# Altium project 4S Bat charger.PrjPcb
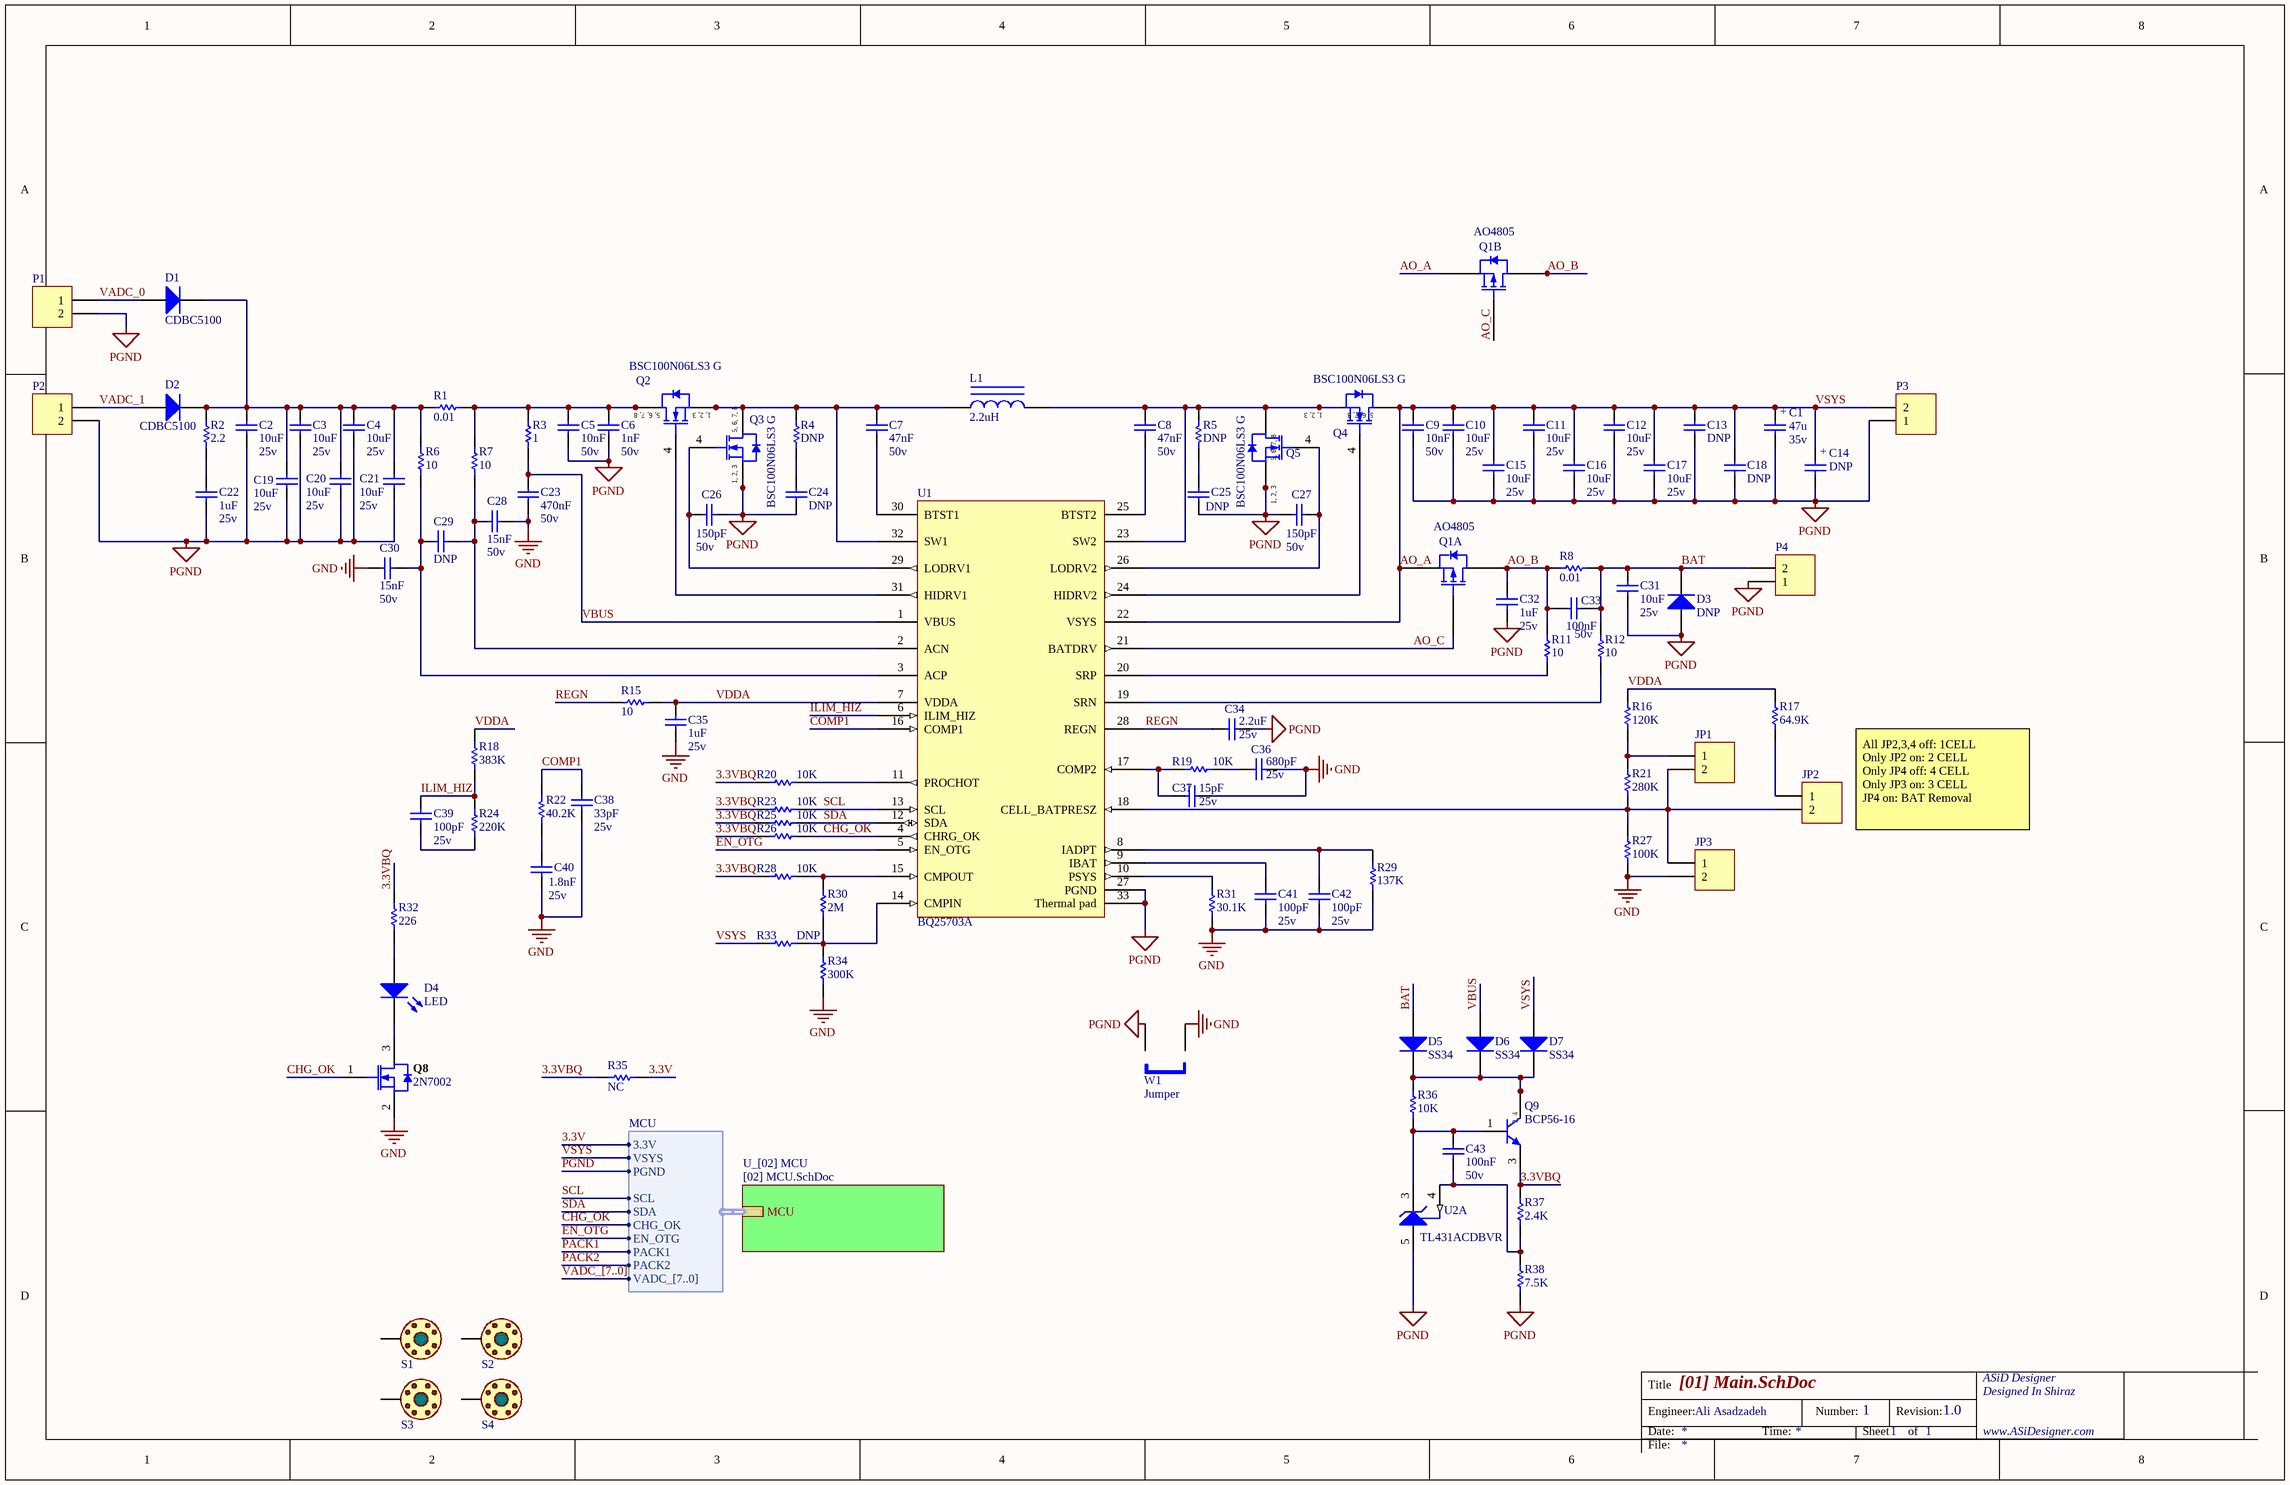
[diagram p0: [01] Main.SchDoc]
2 sheets, 150 parts. Net scope: hierarchical (ports join the sheet entries above them; power ports are global).
Board file: 4S Bat charger.PcbDoc
Sheets:
  [01] Main.SchDoc
    U_[02] MCU = [02] MCU.SchDoc

## Sheet [01] Main.SchDoc: Design 1
size Tabloid; Engineer: The ASID Designer; Organization: ASID Designer; Address1: Iran; Address2: Shiraz; Address3: P.O.Box 71765-385; DocumentNumber: 1; Revision: 1.0; SheetNumber: 1; SheetTotal: 1

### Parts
C1  Volte: 35v  [MY_SMC_D]  (hidden comment: 47u)
C2  Volte: 25v  [MY_0805]  (hidden comment: 10uF)
C3  Volte: 25v  [MY_0805]  (hidden comment: 10uF)
C4  Volte: 25v  [MY_0805]  (hidden comment: 10uF)
C5  Volte: 50v  [MY_0805]  (hidden comment: 10nF)
C6  Volte: 50v  [MY_0805]  (hidden comment: 1nF)
C7  Volte: 50v  [MY_0805]  (hidden comment: 47nF)
C8  Volte: 50v  [MY_0805]  (hidden comment: 47nF)
C9  Volte: 50v  [MY_0805]  (hidden comment: 10nF)
C10  Volte: 25v  [MY_0805]  (hidden comment: 10uF)
C11  Volte: 25v  [MY_0805]  (hidden comment: 10uF)
C12  Volte: 25v  [MY_0805]  (hidden comment: 10uF)
C13  DNP  [MY_0805]
C14  DNP  [MY_SMC_D]
C15  Volte: 25v  [MY_0805]  (hidden comment: 10uF)
C16  Volte: 25v  [MY_0805]  (hidden comment: 10uF)
C17  Volte: 25v  [MY_0805]  (hidden comment: 10uF)
C18  DNP  [MY_0805]
C19  Volte: 25v  [MY_0805]  (hidden comment: 10uF)
C20  Volte: 25v  [MY_0805]  (hidden comment: 10uF)
C21  Volte: 25v  [MY_0805]  (hidden comment: 10uF)
C22  Volte: 25v  [MY_0805]  (hidden comment: 1uF)
C23  Volte: 50v  [MY_0805]  (hidden comment: 470nF)
C24  DNP  [MY_0805]
C25  DNP  [MY_0805]
C26  Volte: 50v  [MY_0805]  (hidden comment: 150pF)
C27  Volte: 50v  [MY_0805]  (hidden comment: 150pF)
C28  Volte: 50v  [MY_0805]  (hidden comment: 15nF)
C29  DNP  [MY_0805]
C30  Volte: 50v  [MY_0805]  (hidden comment: 15nF)
C31  Volte: 25v  [MY_0805]  (hidden comment: 10uF)
C32  Volte: 25v  [MY_0805]  (hidden comment: 1uF)
C33  Volte: 50v  [MY_0805]  (hidden comment: 100nF)
C34  Volte: 25v  [MY_0805]  (hidden comment: 2.2uF)
C35  Volte: 25v  [MY_0805]  (hidden comment: 1uF)
C36  Volte: 25v  [MY_0805]  (hidden comment: 680pF)
C37  Volte: 25v  [MY_0805]  (hidden comment: 15pF)
C38  Volte: 25v  [MY_0805]  (hidden comment: 33pF)
C39  Volte: 25v  [MY_0805]  (hidden comment: 100pF)
C40  Volte: 25v  [MY_0805]  (hidden comment: 1.8nF)
C41  Volte: 25v  [MY_0805]  (hidden comment: 100pF)
C42  Volte: 25v  [MY_0805]  (hidden comment: 100pF)
C43  Volte: 50v  [MY_0805]  (hidden comment: 100nF)
D1  CDBC5100  [MY_SMC]
D2  CDBC5100  [MY_SMC]
D3  DNP  [MY_SMB]
D4  LED  [MY_LED_0805]
D5  SS34  [MY_SMB]
D6  SS34  [MY_SMB]
D7  SS34  [MY_SMB]
JP1  Header 2  [My_1X02]  (value not drawn)
JP2  Header 2  [My_1X02]  (value not drawn)
JP3  Header 2  [My_1X02]  (value not drawn)
L1  2.2uH  [L5mm]
P1  Header 2  [MY_MSTBA2]  (value not drawn)
P2  Header 2  [MY_MSTBA2]  (value not drawn)
P3  Header 2  [MY_MSTBA2]  (value not drawn)
P4  Header 2  [MY_MSTBA2]  (value not drawn)
Q1  AO4805  [My_SOIC_P8]  (parts A,B of 2)
Q2  BSC100N06LS3 G  [INF-PG-TDSON-8-1_V]
Q3  BSC100N06LS3 G  [INF-PG-TDSON-8-1_V]
Q4  BSC100N06LS3 G  [INF-PG-TDSON-8-1_V]
Q5  BSC100N06LS3 G  [INF-PG-TDSON-8-1_V]
Q8  2N7002  [INF-PG-SOT23_N]
Q9  BCP56-16  [INF-SOT223_SC-73_N]
R1  0.01  [MY_2010]
R2  2.2  [MY_1206]
R3  1  [MY_0805]
R4  DNP  [MY_0805]
R5  DNP  [MY_0805]
R6  10  [MY_0805]
R7  10  [MY_0805]
R8  0.01  [MY_2010]
R11  10  [MY_0805]
R12  10  [MY_0805]
R15  10  [MY_0805]
R16  120K  [MY_0805]
R17  64.9K  [MY_0805]
R18  383K  [MY_0805]
R19  10K  [MY_0805]
R20  10K  [MY_0805]
R21  280K  [MY_0805]
R22  40.2K  [MY_0805]
R23  10K  [MY_0805]
R24  220K  [MY_0805]
R25  10K  [MY_0805]
R26  10K  [MY_0805]
R27  100K  [MY_0805]
R28  10K  [MY_0805]
R29  137K  [MY_0805]
R30  2M  [MY_0805]
R31  30.1K  [MY_0805]
R32  226  [MY_0805]
R33  DNP  [MY_0805]
R34  300K  [MY_0805]
R35  NC  [MY_0805]
R36  10K  [MY_0805]
R37  2.4K  [MY_0805]
R38  7.5K  [MY_0805]
S1  Screw  [MY_PAD_3MM]  (value not drawn)  (net tie, no BOM)
S2  Screw  [MY_PAD_3MM]  (value not drawn)  (net tie, no BOM)
S3  Screw  [MY_PAD_3MM]  (value not drawn)  (net tie, no BOM)
S4  Screw  [MY_PAD_3MM]  (value not drawn)  (net tie, no BOM)
U1  BQ25703A  [QFN40P400X400X80_HS-33N]
U2  TL431ACDBVR  [TI-DBV5_N]  (part A of 2)
W1  Jumper  [MY_0805]

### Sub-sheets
U_[02] MCU = [02] MCU.SchDoc: MCU (harness MCU)

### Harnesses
MCU: VSYS, PGND, SCL, SDA, CHG_OK, EN_OTG, PACK1, PACK2, 3.3V, VADC_[7..0]

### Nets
GND: C23.2 C28.1 C30.2 C35.1 C36.2 C37.2 C38.2 C40.2 C41.1 C42.1 JP3.2 Q8.2(SOURCE) R27.1 R29.1 R31.1 R34.1 W1.1
PGND: C1.- C2.1 C3.1 C4.1 C5.2 C6.2 C9.2 C10.1 C11.1 C12.1 C13.1 C14.- C15.1 C16.1 C17.1 C18.1 C19.1 C20.1 C21.1 C22.1 C24.1 C25.1 C26.2 C27.2 C31.1 C32.1 C34.2 D3.A P1.2 P2.2 P3.1 P4.1 Q3.1(SOURCE) Q3.2(SOURCE) Q3.3(SOURCE) Q5.1(SOURCE) Q5.2(SOURCE) Q5.3(SOURCE) R38.2 U1.27(PGND) U1.33(Thermal_pad) U2.5(ANODE) W1.2 ; sheet U_[02] MCU/MCU.PGND
3.3V: R35.2 ; sheet U_[02] MCU/MCU.3.3V
3.3VBQ: Q9.3(E) R20.2 R23.2 R25.2 R26.2 R28.2 R32.1 R35.1 R37.1
AO_A: C1.+ C9.1 C10.2 C11.2 C12.2 C13.2 C14.+ C15.2 C16.2 C17.2 C18.2 D7.A P3.2 Q1.1 Q1.3 Q4.5(DRAIN) Q4.6(DRAIN) Q4.7(DRAIN) Q4.8(DRAIN) R33.2 U1.22(VSYS) ; sheet U_[02] MCU/MCU.VSYS  [also labelled VSYS]
AO_B: C32.2 C33.1 Q1.5 Q1.6 Q1.7 Q1.8 R8.1 R11.1
AO_C: Q1.2 Q1.4 U1.21(BATDRV)
BAT: C31.2 C33.2 D3.K D5.A P4.2 R8.2 R12.1
CHG_OK: Q8.1(GATE) R26.1 U1.4(CHRG_OK) ; sheet U_[02] MCU/MCU.CHG_OK
COMP1: C38.1 R22.1 U1.16(COMP1)
EN_OTG: U1.5(EN_OTG) ; sheet U_[02] MCU/MCU.EN_OTG
ILIM_HIZ: C39.2 R18.1 R24.2 U1.6(ILIM_HIZ)
REGN: C34.1 R15.1 U1.28(REGN)
SCL: R23.1 U1.13(SCL) ; sheet U_[02] MCU/MCU.SCL
SDA: R25.1 U1.12(SDA) ; sheet U_[02] MCU/MCU.SDA
VADC_0: D1.A P1.1
VADC_1: D2.A P2.1
VBUS: C23.1 D6.A R3.1 U1.1(VBUS)
VDDA: C35.2 R15.2 R16.2 R17.2 R18.2 U1.7(VDDA)
NetC2_2: C2.2 C3.2 C4.2 C19.2 C20.2 C21.2 D1.K D2.K R1.1 R2.1 R6.1
NetC5_1: C5.1 C6.1 Q2.5(DRAIN) Q2.6(DRAIN) Q2.7(DRAIN) Q2.8(DRAIN) R1.2 R3.2 R7.1
NetC7_1: C7.1 U1.30(BTST1)
NetC7_2: C7.2 L1.1 Q2.1(SOURCE) Q2.2(SOURCE) Q2.3(SOURCE) Q3.5(DRAIN) Q3.6(DRAIN) Q3.7(DRAIN) Q3.8(DRAIN) R4.1 U1.32(SW1)
NetC8_1: C8.1 U1.25(BTST2)
NetC8_2: C8.2 L1.2 Q4.1(SOURCE) Q4.2(SOURCE) Q4.3(SOURCE) Q5.5(DRAIN) Q5.6(DRAIN) Q5.7(DRAIN) Q5.8(DRAIN) R5.1 U1.23(SW2)
NetC22_2: C22.2 R2.2
NetC24_2: C24.2 R4.2
NetC25_2: C25.2 R5.2
NetC26_1: C26.1 Q3.4(GATE) U1.29(LODRV1)
NetC27_1: C27.1 Q5.4(GATE) U1.26(LODRV2)
NetC28_2: C28.2 C29.2 R7.2 U1.2(ACN)
NetC29_1: C29.1 C30.1 R6.2 U1.3(ACP)
NetC36_1: C36.1 R19.2
NetC37_1: C37.1 R19.1 U1.17(COMP2)
NetC39_1: C39.1 R24.1
NetC40_1: C40.1 R22.2
NetC41_2: C41.2 U1.9(IBAT)
NetC42_2: C42.2 R29.2 U1.8(IADPT)
NetC43_1: C43.1 R37.2 R38.1 U2.4(REF)
NetC43_2: C43.2 Q9.1(B) R36.2 U2.3(CATHODE)
NetD4_A: D4.A R32.2
NetD4_K: D4.K Q8.3(DRAIN)
NetD5_K: D5.K D6.K D7.K Q9.2(C) Q9.4(C) R36.1
NetJP1_1: JP1.1 R16.1 R21.2
NetJP1_2: JP1.2 JP2.2 JP3.1 R21.1 R27.2 U1.18(CELL_BATPRESZ)
NetJP2_1: JP2.1 R17.1
NetQ2_4: Q2.4(GATE) U1.31(HIDRV1)
NetQ4_4: Q4.4(GATE) U1.24(HIDRV2)
NetR11_2: R11.2 U1.20(SRP)
NetR12_2: R12.2 U1.19(SRN)
NetR20_1: R20.1 U1.11(PROCHOT)
NetR28_1: R28.1 R30.1 U1.15(CMPOUT)
NetR30_2: R30.2 R33.1 R34.2 U1.14(CMPIN)
NetR31_2: R31.2 U1.10(PSYS)

Not connected (* = marked no-connect by the designer): S1 0; S2 0; S3 0; S4 0

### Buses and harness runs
bus VADC_[7..0]

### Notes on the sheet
- All JP2,3,4 off: 1CELL
  Only JP2 on: 2 CELL
  Only JP4 off: 4 CELL
  Only JP3 on: 3 CELL
  JP4 on: BAT Removal

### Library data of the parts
C1 = Cap Pol: Polar capacitor; ASiD Part Number: C-AS
C2-C12 C15-C17 C19-C23 C26-C28 C30-C43 = Cap ceramic: None polar capacitor; ASiD Part Number: C-AS
C13 C18 = Cap ceramic: None polar capacitor; ASiD Part Number: C-AS; Volte: 25v
C14 = Cap Pol: Polar capacitor; ASiD Part Number: C-AS; Volte: 35v
C24 C25 C29 = Cap ceramic: None polar capacitor; ASiD Part Number: C-AS; Volte: 50v
D1-D3 D5-D7 = 1N4007: 1 Amp Diode; ASiD Part Number: 1n4007-AS
D4 = LED: Typical INFRARED GaAs LED; ASiD Part Number: LED-AS
JP1-JP3 P1-P4 = Header 2: Header, 2-Pin; ASiD Part Number: Header 2-AS
L1 = INDUCTOR IRON: Power Inductor 1uH
Q2-Q5 = BSC100N06LS3 G: N-Channel OptiMOS 3 Power-Transistor, 60 V VDS, 50 A ID, -55 to 150 degC, PG-TDSON-8-1, Reel, Green; Manufacturer: Infineon; Green: TRUE; ID (max): 50 A; IDpuls (max): 200 A; Polarity: N; Ptot (max): 50 W; QG: 15 nC; RDS (on) (max): 10 mOhm; RDS (on) (max) (@4.5V): 17.9 mOhm; Rth: 2.5 K/W; RthJA (max): 62 K/W; VDS (max): 60 V; VGS(th) (max): 2.2 V; VGS(th) (min): 1.2 V
Q8 = 2N7002: N-Channel OptiMOS Small-Signal-Transistor, 60 V VDS, 0.3 A ID, -55 to 150 degC, PG-SOT23, Reel, Green; Manufacturer: Infineon; Green: TRUE; ID (max): 0.3 A; IDpuls (max): 1.2 A; Ptot (max): 0.5 W; QG: 0.4 nC; RDS (on) (max): 3,000 mOhm; RDS (on) (max) (@4.5V): 4,000 mOhm; RthJA (max): 250 K/W; VDS (max): 60 V; VGS(th) (max): 2.5 V; VGS(th) (min): 1.5 V
Q9 = BCP56-16: NPN Silicon AF Transistor, 80 V VCEO, 1000 mA IC, SOT223, Reel, Green; Manufacturer: Infineon; fT (typ): 100 MHz; Green: TRUE; IC: 1,000 mA; ICBO (max): 100 nA; ICM (max): 1,500 mA; Ptot (max): 2,000 mW; VCBO (max): 100 V; VCE: 2 V; VCEO (max): 80 V; VEBO (max): 5 V
R1-R8 R11 R12 R15-R38 = Res: Standard resistor; ASiD Part Number: Res-AS
S1-S4 = Screw: 3mm Screw; ASiD Part Number: Screw-AS
U1 = BQ25703A: I2C Multi-Chemistry Battery Buck-Boost Charge Controller With System Power / Monitor and Processor Hot Monitor
U2 = TL431ACDBVR: Adjustable Precision Shunt Regulator, 34 ppm / degC, 100 mA, 0 to 70 degC, 5-pin SOT-23 (DBV), Green (RoHS & no Sb/Br); Manufacturer: Texas Instruments; Iout/Iz(Max)(mA): 100; Min Iz for Regulation(uA): 600; Rating: Catalog; SubFamily: Shunt Voltage Reference; Temp Coeff(Max)(ppm/ degree C): 92; Temp Coeff(Typ)(ppm/ degree C): 34; VO Adj(Max)(V): 36; VO Adj(Min)(V): 2.495
W1 = Jumper: Jumper Wire; ASiD Part Number: Jumper-AS

## Sheet [02] MCU.SchDoc: Design 1
size Tabloid; Engineer: The ASID Designer; Organization: ASID Designer; Address1: Iran; Address2: Shiraz; Address3: P.O.Box 71765-385; DocumentNumber: 1; Revision: 1.0; SheetNumber: 1; SheetTotal: 1
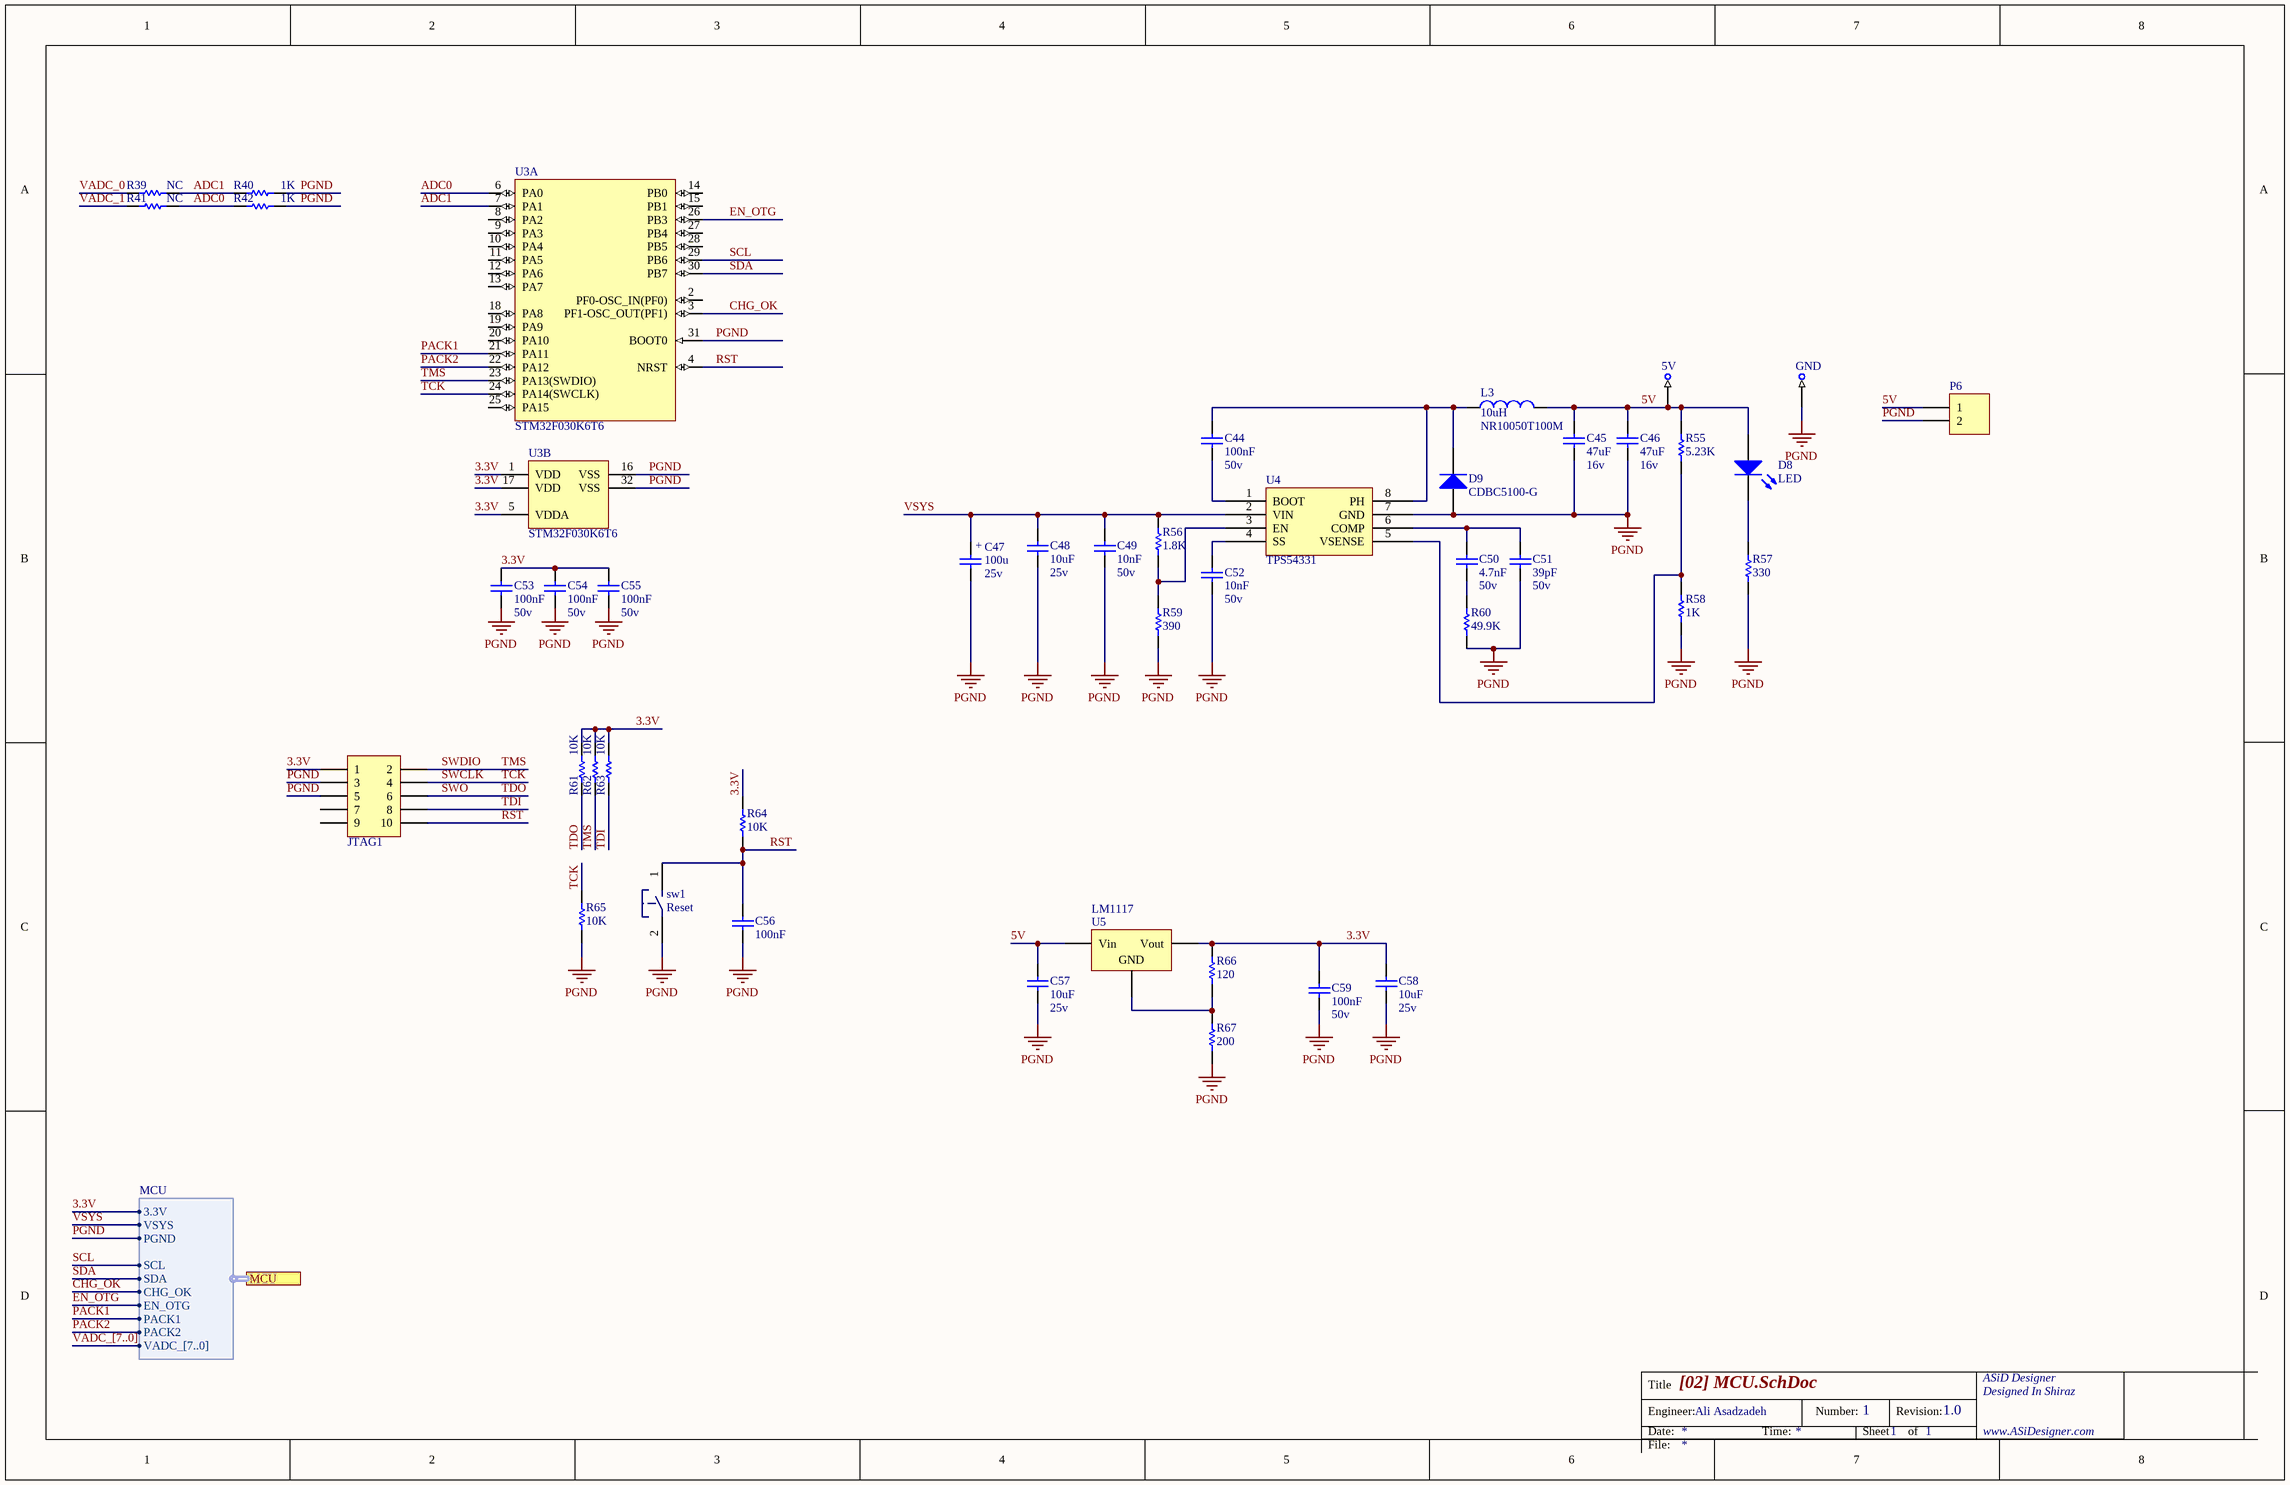
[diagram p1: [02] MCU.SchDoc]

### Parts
C44  Volte: 50v  [MY_0805]  (hidden comment: 100nF)
C45  Volte: 16v  [MY_1206]  (hidden comment: 47uF)
C46  Volte: 16v  [MY_1206]  (hidden comment: 47uF)
C47  Volte: 25v  [MY_E2.5-6mm]  (hidden comment: 100u)
C48  Volte: 25v  [MY_1206]  (hidden comment: 10uF)
C49  Volte: 50v  [MY_0805]  (hidden comment: 10nF)
C50  Volte: 50v  [MY_0805]  (hidden comment: 4.7nF)
C51  Volte: 50v  [MY_0805]  (hidden comment: 39pF)
C52  Volte: 50v  [MY_0805]  (hidden comment: 10nF)
C53  Volte: 50v  [MY_0805]  (hidden comment: 100nF)
C54  Volte: 50v  [MY_0805]  (hidden comment: 100nF)
C55  Volte: 50v  [MY_0805]  (hidden comment: 100nF)
C56  100nF  [MY_0805]
C57  Volte: 25v  [MY_0805]  (hidden comment: 10uF)
C58  Volte: 25v  [MY_0805]  (hidden comment: 10uF)
C59  Volte: 50v  [MY_0805]  (hidden comment: 100nF)
D8  LED  [MY_LED_0805]
D9  CDBC5100-G  [MY_SMC]
JTAG1  Header 5X2  [MY_2X05_BOX]  (value not drawn)
L3  NR10050T100M  value 10uH  [MY_DR1030]
P6  Header 2  [MY_MSTBA2]  (value not drawn)
R39  NC  [MY_0805]
R40  1K  [MY_0805]
R41  NC  [MY_0805]
R42  1K  [MY_0805]
R55  5.23K  [MY_0805]
R56  1.8K  [MY_0805]
R57  330  [MY_0805]
R58  1K  [MY_0805]
R59  390  [MY_0805]
R60  49.9K  [MY_0805]
R61  10K  [MY_0805]
R62  10K  [MY_0805]
R63  10K  [MY_0805]
R64  10K  [MY_0805]
R65  10K  [MY_0805]
R66  120  [MY_0805]
R67  200  [MY_0805]
sw1  Reset  [MY_PB-SMD]
TP1  5V  [MY_TestPin]  (no BOM)
TP2  GND  [MY_TestPin]  (no BOM)
U3  STM32F030K6T6  [STM-LQFP32_N]  (parts A,B of 2)
U4  TPS54331  [My_SOIC_P8_powerPad]
U5  LM1117  [MY_SOT223]

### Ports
MCU (harness MCU)

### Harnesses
MCU: VSYS, PGND, SCL, SDA, CHG_OK, EN_OTG, PACK1, PACK2, 3.3V, VADC_[7..0]

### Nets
PGND: C45.1 C46.1 C47.- C48.1 C49.1 C51.1 C52.1 C53.1 C54.1 C55.1 C56.1 C57.1 C58.1 C59.1 D9.A JTAG1.3 JTAG1.5 P6.2 R40.2 R42.2 R57.2 R58.2 R59.2 R60.2 R65.2 R67.2 sw1.2 TP2.1 U3.16(VSS) U3.31(BOOT0) U3.32(VSS) U4.7(GND) ; port MCU.PGND
3.3V: C53.2 C54.2 C55.2 C58.2 C59.2 JTAG1.1 R61.1 R62.1 R63.1 R64.1 R66.1 U3.1(VDD) U3.5(VDDA) U3.17(VDD) U5.2(Vout) ; port MCU.3.3V
5V: C45.2 C46.2 C57.2 D8.A L3.2 P6.1 R55.1 TP1.1 U5.3(Vin)
ADC0: R41.2 R42.1 U3.6(PA0)
ADC1: R39.2 R40.1 U3.7(PA1)
CHG_OK: U3.3(PF1-OSC_OUT(PF1)) ; port MCU.CHG_OK
EN_OTG: U3.26(PB3) ; port MCU.EN_OTG
PACK1: U3.21(PA11) ; port MCU.PACK1
PACK2: U3.22(PA12) ; port MCU.PACK2
RST: C56.2 JTAG1.10 R64.2 sw1.1 U3.4(NRST)
SCL: U3.29(PB6) ; port MCU.SCL
SDA: U3.30(PB7) ; port MCU.SDA
SWCLK: JTAG1.4 R65.1 U3.24(PA14(SWCLK))  [also labelled TCK]
SWDIO: JTAG1.2 R62.2 U3.23(PA13(SWDIO))  [also labelled TMS]
SWO: JTAG1.6 R61.2  [also labelled TDO]
TDI: JTAG1.8 R63.2
VADC_0: R39.1
VADC_1: R41.1
VSYS: C47.+ C48.2 C49.2 R56.1 U4.2(VIN) ; port MCU.VSYS  [project net AO_A]
NetC44_1: C44.1 U4.1(BOOT)
NetC44_2: C44.2 D9.K L3.1 U4.8(PH)
NetC50_1: C50.1 R60.1
NetC50_2: C50.2 C51.2 U4.6(COMP)
NetC52_2: C52.2 U4.4(SS)
NetD8_K: D8.K R57.1
NetR55_2: R55.2 R58.1 U4.5(VSENSE)
NetR56_2: R56.2 R59.1 U4.3(EN)
NetR66_2: R66.2 R67.1 U5.1(GND)

Not connected (* = marked no-connect by the designer): JTAG1 7 9; U3 2(PF0-OSC_IN(PF0)) 8(PA2) 9(PA3) 10(PA4) 11(PA5) 12(PA6) 13(PA7) 14(PB0) 15(PB1) 18(PA8) 19(PA9) 20(PA10) 25(PA15) 27(PB4) 28(PB5)

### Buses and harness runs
bus VADC_[7..0]

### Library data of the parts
C44-C46 C48-C52 = Cap ceramic: None polar capacitor
C47 = Cap Pol: Polar capacitor
C53-C55 C57-C59 = Cap ceramic: as C2 on sheet [01] Main
C56 = Cap ceramic: CAP-100Nf
D8 = LED: Typical INFRARED GaAs LED
D9 = 1N4007: 1 Amp Diode
JTAG1 = Header 5X2: Header, 5-Pin, Dual row
L3 = Inductor: Current: 4.7A
P6 = Header 2: as JP1 on sheet [01] Main
R39-R42 R66 R67 = Res: as R1 on sheet [01] Main
R55-R60 = Res: Standard resistor
R61-R65 = Res: resistor 1/4 wat
sw1 = Tac switch: small tac switch; ASiD Part Number: Tac switch-AS
TP1 TP2 = Test Point
U3 = STM32F030K6T6: ARM Cortex-M0 32-bit MCU, 32 KB Flash, 4 KB Internal RAM, 26 I/Os, 32-pin LQFP, -40 to 85 degC, Tray; FLASH Size (Prog) (kB): 32; I/Os (High Current): 26; Internal RAM Size (kB): 4; Operating Frequency(F) (Processor speed) (MHz): 48; Supply Voltage(Vcc) min (V): 2.4
U4 = TPS54331: 3A, 28V INPUT, STEP DOWN SWIFT™ DC/DC CONVERTER WITH ECO-MODE
U5 = LM1117: Low Drop Voltage Reg; ASiD Part Number: LM1117-AS

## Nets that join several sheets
PGND: [01] Main (43 pins), [02] MCU (32 pins)
3.3V: [01] Main (R35.2), [02] MCU (15 pins)
AO_A: [01] Main (21 pins), [02] MCU (5 pins)
CHG_OK: [01] Main (Q8.1 R26.1 U1.4), [02] MCU (U3.3)
EN_OTG: [01] Main (U1.5), [02] MCU (U3.26)
SCL: [01] Main (R23.1 U1.13), [02] MCU (U3.29)
SDA: [01] Main (R25.1 U1.12), [02] MCU (U3.30)
VADC_0: [01] Main (D1.A P1.1), [02] MCU (R39.1)
VADC_1: [01] Main (D2.A P2.1), [02] MCU (R41.1)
